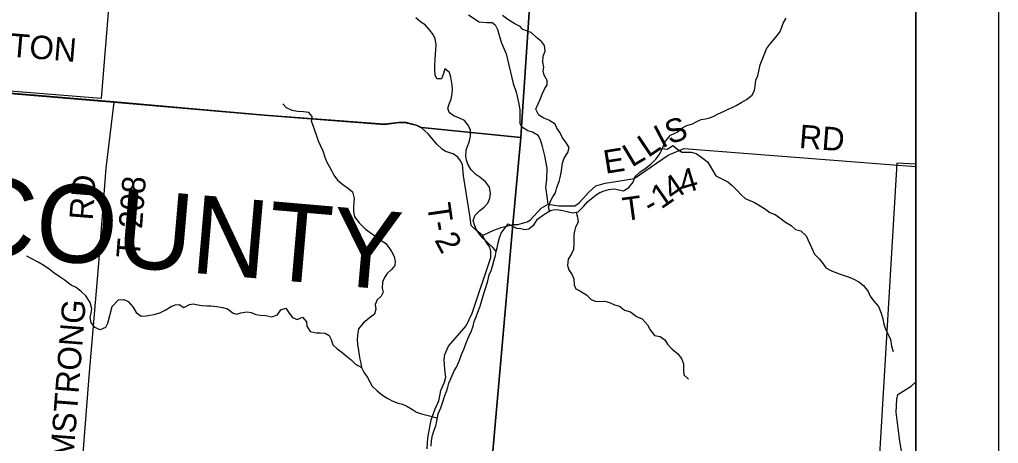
# Model space of a CAD drawing. Extents: x 0 to 42.5, y 0 to 22.
# Drawn here: x 7.815 to 9, y 18.213 to 18.727 of the extents above; entities that cross this region are included whole.
import ezdxf

# ---------------------------------------------------------------- set-up
doc = ezdxf.new("R2010")
doc.units = 0
for name, color, linetype in [('GM_X_County_Text', 7, 'Continuous'), ('GM_X_Interchange_Ramps', 7, 'Continuous'), ('GM_X_Minor_River', 7, 'Continuous'), ('GM_X_Section', 7, 'Continuous'), ('GM_X_Township', 7, 'Continuous'), ('GM_X_Township_Road', 7, 'Continuous'), ('GM_X_Township_Road_Text', 7, 'Continuous'), ('GM_X_Unincorporated', 7, 'Continuous'), ('SH_Cut_Line', 7, 'Continuous'), ('SH_Data', 7, 'Continuous')]:
    doc.layers.add(name, color=color, linetype=linetype)

msp = doc.modelspace()

# ---------------------------------------------------------------- linework, layer by layer
at = {"layer": 'GM_X_Interchange_Ramps'}
for points in [[(7.6874, 18.6472), (7.929, 18.6269), (8.111, 18.6109), (8.2565, 18.5997), (8.2741, 18.602), (8.283, 18.6019), (8.295, 18.5988), (8.3015, 18.5957), (8.4216, 18.5836), (8.4225, 18.5968), (8.4553, 19.0856), (8.4644, 19.2057), (8.5155, 19.8538)], [(8.9, 15.5376), (8.9, 19.0538), (8.8021, 19.0608), (8.7971, 19.0612), (8.4553, 19.0856), (8.4225, 18.5968), (8.4216, 18.5836), (8.4123, 18.4784), (8.3832, 18.1485), (8.3379, 17.6339), (8.308, 17.2922), (8.3087, 17.2846), (8.3084, 17.2765), (8.3074, 17.2694), (8.2902, 17.0877), (8.2877, 17.0646), (8.2823, 16.9912), (8.274, 16.8923), (8.2572, 16.7056), (8.248, 16.5943), (8.2478, 16.5901), (8.1793, 15.7911)]]:
    msp.add_lwpolyline(points, dxfattribs=at)
at = {"layer": 'GM_X_Minor_River'}
for p, q in [((8.4342, 18.711), (8.4242, 18.7146)), ((8.4406, 18.7047), (8.4342, 18.711)), ((8.447, 18.6999), (8.4406, 18.7047)), ((8.4506, 18.695), (8.447, 18.6999)), ((8.4511, 18.6882), (8.4506, 18.695)), ((8.4486, 18.6751), (8.4487, 18.6821)), ((8.4487, 18.6821), (8.4511, 18.6882)), ((8.4496, 18.669), (8.4486, 18.6751)), ((8.449, 18.6643), (8.4496, 18.669)), ((8.4501, 18.6591), (8.449, 18.6643)), ((8.4537, 18.6529), (8.4501, 18.6591)), ((8.4475, 18.6364), (8.4506, 18.6423)), ((8.4506, 18.6423), (8.4536, 18.6477)), ((8.4536, 18.6477), (8.4537, 18.6529)), ((8.4427, 18.6246), (8.4456, 18.6311)), ((8.4456, 18.6311), (8.4475, 18.6364)), ((8.4401, 18.618), (8.4427, 18.6246)), ((8.4436, 18.6108), (8.4401, 18.618)), ((8.4497, 18.607), (8.4436, 18.6108)), ((8.4556, 18.6045), (8.4497, 18.607)), ((8.4633, 18.5999), (8.4556, 18.6045)), ((8.4652, 18.595), (8.4633, 18.5999)), ((8.4695, 18.5893), (8.4652, 18.595)), ((8.4723, 18.5832), (8.4695, 18.5893)), ((8.4763, 18.5779), (8.4723, 18.5832)), ((8.4805, 18.5714), (8.4763, 18.5779)), ((8.4787, 18.5653), (8.4805, 18.5714)), ((8.5931, 18.5704), (8.5995, 18.5696)), ((8.5995, 18.5696), (8.6058, 18.5738)), ((8.6058, 18.5738), (8.6115, 18.5696)), ((8.4722, 18.5527), (8.4741, 18.5587)), ((8.4741, 18.5587), (8.4787, 18.5653)), ((8.6115, 18.5696), (8.6166, 18.5659)), ((8.6166, 18.5659), (8.623, 18.5661)), ((8.623, 18.5661), (8.6281, 18.5659)), ((8.6281, 18.5659), (8.634, 18.5644)), ((8.634, 18.5644), (8.6408, 18.5594)), ((8.6408, 18.5594), (8.6476, 18.5541)), ((8.4707, 18.5409), (8.4714, 18.5464)), ((8.4714, 18.5464), (8.4722, 18.5527)), ((8.6476, 18.5541), (8.6512, 18.5491)), ((8.6512, 18.5491), (8.654, 18.5442)), ((8.4682, 18.5305), (8.4695, 18.5352)), ((8.4695, 18.5352), (8.4707, 18.5409)), ((8.654, 18.5442), (8.658, 18.5373)), ((8.658, 18.5373), (8.6661, 18.5331)), ((8.4637, 18.5168), (8.4655, 18.5231)), ((8.4655, 18.5231), (8.4682, 18.5305)), ((8.6661, 18.5331), (8.6725, 18.5301)), ((8.6725, 18.5301), (8.6778, 18.5253)), ((8.6778, 18.5253), (8.6841, 18.5192)), ((8.4578, 18.5066), (8.4605, 18.5117)), ((8.4605, 18.5117), (8.4637, 18.5168)), ((8.6841, 18.5192), (8.6882, 18.5145)), ((8.6882, 18.5145), (8.6933, 18.5099)), ((8.4553, 18.4991), (8.4578, 18.5066)), ((8.4565, 18.4946), (8.4553, 18.4991)), ((8.6933, 18.5099), (8.699, 18.5074)), ((8.699, 18.5074), (8.7045, 18.5049)), ((8.7045, 18.5049), (8.7094, 18.5019)), ((8.7094, 18.5019), (8.7168, 18.4977)), ((8.4889, 18.4931), (8.4904, 18.4873)), ((8.4904, 18.4873), (8.4913, 18.4809)), ((8.7168, 18.4977), (8.7232, 18.4927)), ((8.7232, 18.4927), (8.7297, 18.4902)), ((8.7297, 18.4902), (8.7355, 18.4862)), ((8.4913, 18.4809), (8.488, 18.475)), ((8.7355, 18.4862), (8.7423, 18.4809)), ((8.7423, 18.4809), (8.7489, 18.4771)), ((8.7489, 18.4771), (8.7544, 18.4723)), ((8.4869, 18.4703), (8.4861, 18.4656)), ((8.4861, 18.4656), (8.4861, 18.4595)), ((8.488, 18.475), (8.4869, 18.4703)), ((8.7544, 18.4723), (8.7607, 18.4706)), ((8.7607, 18.4706), (8.7673, 18.4643)), ((8.7673, 18.4643), (8.7737, 18.4502)), ((8.4859, 18.4546), (8.4856, 18.4481)), ((8.4861, 18.4595), (8.4859, 18.4546)), ((8.4828, 18.4417), (8.4792, 18.4362)), ((8.4856, 18.4481), (8.4828, 18.4417)), ((8.7737, 18.4502), (8.7772, 18.4422)), ((8.7772, 18.4422), (8.7829, 18.4367)), ((8.4792, 18.4362), (8.4784, 18.4284)), ((8.4784, 18.4284), (8.4799, 18.4233)), ((8.7829, 18.4367), (8.788, 18.4306)), ((8.788, 18.4306), (8.7912, 18.4257)), ((8.4799, 18.4233), (8.484, 18.4174)), ((8.484, 18.4174), (8.4859, 18.4123)), ((8.7912, 18.4257), (8.7978, 18.4221)), ((8.7978, 18.4221), (8.8031, 18.4202)), ((8.8031, 18.4202), (8.8086, 18.418)), ((8.8086, 18.418), (8.8143, 18.4159)), ((8.4859, 18.4123), (8.4864, 18.4052)), ((8.4864, 18.4052), (8.4885, 18.4003)), ((8.8143, 18.4159), (8.8192, 18.4142)), ((8.8192, 18.4142), (8.8249, 18.4121)), ((8.8249, 18.4121), (8.8308, 18.4089)), ((8.8308, 18.4089), (8.8368, 18.4043)), ((8.8368, 18.4043), (8.8423, 18.3971)), ((8.4885, 18.4003), (8.4934, 18.3978)), ((8.4934, 18.3978), (8.5014, 18.3929)), ((8.5014, 18.3929), (8.5068, 18.3872)), ((8.8423, 18.3971), (8.8449, 18.3914)), ((8.5068, 18.3872), (8.5119, 18.3852)), ((8.5119, 18.3852), (8.5178, 18.385)), ((8.5178, 18.385), (8.5233, 18.3854)), ((8.5233, 18.3854), (8.529, 18.3835)), ((8.529, 18.3835), (8.5351, 18.3808)), ((8.5351, 18.3808), (8.5411, 18.3792)), ((8.8449, 18.3914), (8.8491, 18.3855)), ((8.8491, 18.3855), (8.8547, 18.3788)), ((8.5411, 18.3792), (8.5474, 18.3745)), ((8.5474, 18.3745), (8.5547, 18.3722)), ((8.5547, 18.3722), (8.5617, 18.3668)), ((8.8547, 18.3788), (8.8581, 18.3706)), ((8.8581, 18.3706), (8.86, 18.364)), ((8.5617, 18.3668), (8.5686, 18.364)), ((8.5686, 18.364), (8.5753, 18.3567)), ((8.86, 18.364), (8.8611, 18.3573)), ((8.8611, 18.3573), (8.863, 18.3526)), ((8.5753, 18.3567), (8.5782, 18.3505)), ((8.5782, 18.3505), (8.5838, 18.3438)), ((8.863, 18.3526), (8.866, 18.3459)), ((8.866, 18.3459), (8.8695, 18.3387)), ((8.5838, 18.3438), (8.5906, 18.3426)), ((8.5906, 18.3426), (8.5961, 18.3386)), ((8.5961, 18.3386), (8.5995, 18.3333)), ((8.5995, 18.3333), (8.6048, 18.3276)), ((8.8695, 18.3387), (8.8707, 18.3309)), ((8.6048, 18.3276), (8.6118, 18.3213)), ((8.6118, 18.3213), (8.6163, 18.3158)), ((8.8707, 18.3309), (8.8727, 18.3243)), ((8.6163, 18.3158), (8.6188, 18.3092)), ((8.6188, 18.3092), (8.6187, 18.3019)), ((8.6187, 18.3019), (8.6193, 18.2961)), ((8.6193, 18.2961), (8.6248, 18.2909))]:
    msp.add_line(p, q, dxfattribs=at)
for points in [[(8.3607, 18.5853), (8.361, 18.5929), (8.3577, 18.5992), (8.3535, 18.6041), (8.3466, 18.6076), (8.3411, 18.6095), (8.3349, 18.614), (8.3336, 18.6193), (8.3353, 18.6253), (8.3375, 18.6303), (8.3387, 18.6369), (8.3389, 18.6418), (8.3388, 18.6471), (8.3379, 18.6519), (8.3371, 18.6568), (8.3353, 18.6623), (8.3298, 18.6669), (8.3283, 18.6611), (8.3259, 18.6546), (8.32, 18.6547), (8.318, 18.6594), (8.3177, 18.6661), (8.3175, 18.6716), (8.3182, 18.6782), (8.3186, 18.685), (8.319, 18.69), (8.3191, 18.6966), (8.318, 18.7031), (8.3156, 18.7084), (8.3113, 18.7141), (8.3058, 18.7203), (8.3009, 18.7233), (8.2947, 18.7289)], [(8.4242, 18.7146), (8.4233, 18.7156), (8.421, 18.7181), (8.4144, 18.7214), (8.4061, 18.7266), (8.3995, 18.7316)], [(8.4066, 18.4791), (8.4164, 18.4738), (8.4219, 18.4732), (8.4266, 18.4722), (8.4313, 18.4728), (8.438, 18.4781), (8.442, 18.4847), (8.4481, 18.489), (8.4528, 18.4924), (8.4576, 18.4952), (8.4625, 18.4966), (8.4678, 18.4962), (8.4726, 18.4954), (8.4796, 18.4935), (8.4849, 18.4923), (8.4911, 18.4936), (8.4978, 18.5), (8.5029, 18.5063), (8.5128, 18.5142), (8.5176, 18.517), (8.5227, 18.5189), (8.5284, 18.5206), (8.5347, 18.5215), (8.546, 18.5192), (8.5525, 18.523), (8.5576, 18.5296), (8.5599, 18.536), (8.5657, 18.5417), (8.5723, 18.5462), (8.579, 18.5513), (8.5852, 18.5573), (8.5891, 18.5628), (8.5919, 18.5679), (8.5942, 18.5729), (8.5969, 18.5791), (8.603, 18.5865), (8.611, 18.5902), (8.6178, 18.5959), (8.6228, 18.5984), (8.6296, 18.6002), (8.6347, 18.6031), (8.64, 18.6053), (8.6454, 18.6064), (8.6507, 18.6077), (8.6554, 18.6096), (8.6607, 18.6122), (8.667, 18.6151), (8.6729, 18.6181), (8.6776, 18.6201), (8.6824, 18.6224), (8.6894, 18.6267), (8.6951, 18.6296), (8.7018, 18.6348), (8.7048, 18.6411), (8.7056, 18.646), (8.7062, 18.6532), (8.7087, 18.6583), (8.7099, 18.6642), (8.7116, 18.6718), (8.7149, 18.6799), (8.7173, 18.6858), (8.7193, 18.6911), (8.724, 18.6975), (8.7305, 18.7053), (8.7353, 18.7115), (8.7379, 18.7174), (8.7395, 18.7221), (8.7429, 18.7284)], [(8.1683, 18.603), (8.1692, 18.6092), (8.1652, 18.614), (8.1588, 18.6148), (8.1514, 18.615), (8.1448, 18.6166), (8.138, 18.6197), (8.1335, 18.6245)], [(8.1684, 18.603), (8.1749, 18.5845), (8.1766, 18.5796), (8.1788, 18.5745), (8.182, 18.5674), (8.1849, 18.5587), (8.1869, 18.5538), (8.19, 18.5483), (8.1926, 18.5435), (8.1955, 18.5382), (8.1998, 18.5321), (8.2062, 18.5268), (8.2131, 18.522), (8.2178, 18.518), (8.2201, 18.5099), (8.2197, 18.5051), (8.2193, 18.4989), (8.2193, 18.4939), (8.2204, 18.4877), (8.2259, 18.4803), (8.2337, 18.4727), (8.2393, 18.4685), (8.2477, 18.4624), (8.2526, 18.4588), (8.2581, 18.4557), (8.2619, 18.4504), (8.2653, 18.4457), (8.2683, 18.4396), (8.2698, 18.4333), (8.2694, 18.4286), (8.2651, 18.4236), (8.2596, 18.4183), (8.2563, 18.4132), (8.2544, 18.4085), (8.254, 18.4011), (8.2553, 18.3963), (8.2529, 18.3912), (8.2479, 18.3869), (8.2456, 18.3812), (8.2462, 18.3757), (8.2445, 18.3694), (8.238, 18.3647), (8.231, 18.3588), (8.2253, 18.3518), (8.2241, 18.3442), (8.2237, 18.3383), (8.2241, 18.333), (8.2252, 18.3254), (8.226, 18.3199), (8.2269, 18.315), (8.2281, 18.31), (8.2288, 18.3051), (8.2316, 18.2992), (8.236, 18.2926), (8.2388, 18.2876), (8.242, 18.2821), (8.2479, 18.2766), (8.2545, 18.2715), (8.2606, 18.2673), (8.2669, 18.2639), (8.2733, 18.2618), (8.2784, 18.2604), (8.2837, 18.2581), (8.2906, 18.2541), (8.2955, 18.2507), (8.3017, 18.2486), (8.308, 18.2471), (8.3206, 18.2437)], [(8.392, 18.4454), (8.3879, 18.4502), (8.3822, 18.4557), (8.3757, 18.4618), (8.3718, 18.4667), (8.3682, 18.4716), (8.3659, 18.4766), (8.3642, 18.483), (8.3667, 18.4897), (8.372, 18.4952), (8.3773, 18.4991), (8.3817, 18.5039), (8.3844, 18.5101), (8.3851, 18.516), (8.384, 18.5234), (8.3789, 18.5301), (8.3721, 18.5356), (8.3673, 18.5388), (8.3617, 18.5445), (8.3575, 18.5514), (8.356, 18.5561), (8.3554, 18.5612), (8.3556, 18.5682), (8.3572, 18.573), (8.3592, 18.5779), (8.3607, 18.5853)], [(8.3132, 18.2097), (8.3138, 18.2161), (8.315, 18.2228), (8.3167, 18.2288), (8.3188, 18.234), (8.3199, 18.2397), (8.3217, 18.2486), (8.3249, 18.2562), (8.3274, 18.2634), (8.3299, 18.2708), (8.3316, 18.2757), (8.3335, 18.2812), (8.3348, 18.2861), (8.3375, 18.2924), (8.3409, 18.3007), (8.3438, 18.3055), (8.3472, 18.3127), (8.3499, 18.3206), (8.3531, 18.3278), (8.3558, 18.3348), (8.359, 18.3426), (8.3619, 18.3494), (8.364, 18.3551), (8.3653, 18.3606), (8.3678, 18.3665), (8.3699, 18.3718), (8.3724, 18.3794), (8.3741, 18.3849), (8.3762, 18.3917), (8.3779, 18.397), (8.38, 18.4031), (8.3817, 18.4101), (8.3836, 18.4173), (8.3859, 18.4225), (8.3874, 18.4278), (8.3895, 18.4355), (8.3911, 18.4405), (8.392, 18.4454), (8.393, 18.4501), (8.3945, 18.4562), (8.396, 18.4621), (8.3981, 18.4678), (8.4063, 18.479)], [(7.9265, 18.3784), (7.9214, 18.3583), (7.9189, 18.3532), (7.9124, 18.3505), (7.9062, 18.3533), (7.9017, 18.3596), (7.9005, 18.3654), (7.9017, 18.3713), (7.9023, 18.3761), (7.9002, 18.3837), (7.895, 18.3919), (7.8897, 18.3967), (7.8836, 18.402), (7.8775, 18.4047), (7.8691, 18.4111), (7.8641, 18.4145), (7.8565, 18.4195), (7.8509, 18.4239), (7.8444, 18.4284), (7.8376, 18.4324), (7.8299, 18.4368), (7.8236, 18.4397)], [(7.9265, 18.3784), (7.9345, 18.3869), (7.941, 18.3873), (7.9463, 18.3848), (7.9521, 18.3785), (7.9561, 18.3717), (7.962, 18.3671), (7.9681, 18.3675), (7.9728, 18.3684), (7.9779, 18.369), (7.9846, 18.3712), (7.9912, 18.3743), (7.9984, 18.379), (8.0032, 18.3809), (8.0081, 18.3813), (8.0136, 18.3776), (8.0208, 18.3814), (8.0256, 18.3822), (8.0307, 18.3808), (8.0356, 18.3799), (8.0417, 18.3795), (8.0464, 18.3795), (8.0538, 18.3789), (8.0605, 18.3776), (8.0665, 18.376), (8.0734, 18.3709), (8.0781, 18.3697), (8.083, 18.3711), (8.0902, 18.3722), (8.0952, 18.3716), (8.1009, 18.3693), (8.1064, 18.3684), (8.113, 18.3678), (8.1202, 18.3662), (8.127, 18.3689), (8.1314, 18.3746), (8.1373, 18.3768), (8.1413, 18.3706), (8.1453, 18.3656), (8.1509, 18.3631), (8.1574, 18.3658), (8.1621, 18.3601), (8.1629, 18.3551), (8.1668, 18.3487), (8.1744, 18.3468), (8.1794, 18.3468), (8.1849, 18.3464), (8.1898, 18.3437), (8.1923, 18.339), (8.1941, 18.3323), (8.1993, 18.3276), (8.2049, 18.3234), (8.2104, 18.319), (8.2165, 18.3142), (8.2218, 18.3089), (8.2288, 18.3051)]]:
    msp.add_lwpolyline(points, dxfattribs=at)
at = {"layer": 'GM_X_Section'}
msp.add_lwpolyline([(7.4474, 19.1773), (7.955, 19.138), (7.9137, 18.631), (7.4421, 18.6691), (7.4064, 18.6718)], close=True, dxfattribs=at)
at = {"layer": 'GM_X_Township'}
msp.add_lwpolyline([(7.6874, 18.6472), (7.929, 18.6269), (8.111, 18.6109), (8.2565, 18.5997), (8.2741, 18.602), (8.283, 18.6019), (8.295, 18.5988), (8.3015, 18.5957), (8.4216, 18.5836), (8.4123, 18.4784), (8.3832, 18.1485), (8.3379, 17.6339), (8.308, 17.2922)], dxfattribs=at)
at = {"layer": 'GM_X_Township_Road'}
msp.add_line((7.9292, 18.6266), (7.9617, 18.6238), dxfattribs=at)
for points in [[(8.3585, 18.7322), (8.3714, 18.7239), (8.3806, 18.723), (8.387, 18.723), (8.3907, 18.7202), (8.3935, 18.7147), (8.3981, 18.6991), (8.4039, 18.685), (8.4125, 18.6492), (8.416, 18.6385), (8.4194, 18.6245), (8.4207, 18.6169), (8.4204, 18.6009), (8.4226, 18.5966)], [(7.3505, 18.6762), (7.4024, 18.6716), (7.4512, 18.6662), (7.5068, 18.6617), (7.5691, 18.6559), (7.6875, 18.6469), (7.9292, 18.6266)], [(7.9292, 18.6266), (7.9194, 18.5467), (7.9101, 18.4262), (7.8988, 18.2941), (7.8789, 18.0407)], [(7.9617, 18.6238), (8.1112, 18.6107), (8.2566, 18.5994), (8.2742, 18.6017), (8.2831, 18.6016), (8.2951, 18.5985), (8.3016, 18.5954)], [(8.3753, 18.4648), (8.3648, 18.4736), (8.3615, 18.4769), (8.3599, 18.4893), (8.3524, 18.5373), (8.3511, 18.551), (8.3488, 18.5552), (8.3454, 18.5597), (8.3399, 18.5637), (8.3307, 18.5668), (8.3264, 18.5695), (8.32, 18.5756), (8.3098, 18.588), (8.3016, 18.5954)], [(8.455, 18.5028), (8.4538, 18.512), (8.4522, 18.5234), (8.4533, 18.5327), (8.4535, 18.5464), (8.451, 18.5614), (8.4479, 18.5726), (8.4455, 18.5807), (8.4429, 18.586), (8.4359, 18.5901), (8.4304, 18.5917), (8.4226, 18.5966)], [(8.4124, 18.4782), (8.4181, 18.4782), (8.4295, 18.4813), (8.4333, 18.4837), (8.4466, 18.4982), (8.455, 18.5028), (8.4678, 18.501), (8.4777, 18.5009), (8.487, 18.5007), (8.4925, 18.5043), (8.5045, 18.518), (8.5124, 18.5251), (8.5238, 18.5284), (8.5467, 18.5318), (8.559, 18.5339), (8.6003, 18.5621), (8.6192, 18.5704), (8.868, 18.5509), (8.9, 18.5484)], [(8.3753, 18.4648), (8.389, 18.4712), (8.3978, 18.4744), (8.4124, 18.4782)], [(8.3082, 18.2062), (8.3093, 18.2195), (8.3134, 18.2415), (8.3181, 18.2546), (8.3224, 18.2646), (8.3241, 18.2727), (8.325, 18.277), (8.3293, 18.2872), (8.3311, 18.293), (8.3299, 18.3024), (8.3289, 18.3145), (8.3296, 18.3208), (8.3344, 18.3308), (8.3558, 18.3553), (8.3628, 18.3708), (8.3856, 18.4384), (8.3853, 18.446), (8.3844, 18.4506), (8.38, 18.4569), (8.3753, 18.4648)], [(8.8846, 18.191), (8.8801, 18.2183), (8.8762, 18.2508), (8.8769, 18.2665), (8.8784, 18.2723), (8.8943, 18.2822), (8.9, 18.2874)]]:
    msp.add_lwpolyline(points, dxfattribs=at)
at = {"layer": 'GM_X_Unincorporated'}
msp.add_lwpolyline([(8.9, 18.101), (8.9, 18.5512), (8.8772, 18.5527), (8.8503, 18.1041)], close=True, dxfattribs=at)
at = {"layer": 'SH_Cut_Line'}
for points in [[(7.6874, 18.6472), (7.929, 18.6269), (8.111, 18.6109), (8.2565, 18.5997), (8.2741, 18.602), (8.283, 18.6019), (8.295, 18.5988), (8.3015, 18.5957), (8.4216, 18.5836), (8.4225, 18.5968), (8.4553, 19.0856), (8.7971, 19.0612), (8.8021, 19.0608), (8.9, 19.0538), (8.9, 20.9)], [(8.9, 14.1), (8.9, 19.0538), (8.8021, 19.0608), (8.7971, 19.0612), (8.4553, 19.0856), (8.4225, 18.5968), (8.4216, 18.5836), (8.4123, 18.4784), (8.3832, 18.1485), (8.3379, 17.6339), (8.308, 17.2922), (8.3087, 17.2846), (8.3084, 17.2765), (8.3074, 17.2694), (8.2902, 17.0877), (8.2877, 17.0646), (8.2823, 16.9912), (8.274, 16.8923), (8.2572, 16.7056), (8.248, 16.5943), (8.2478, 16.5901), (8.1793, 15.7911)], [(8.308, 17.2922), (8.3379, 17.6339), (8.3832, 18.1485), (8.4123, 18.4784), (8.4216, 18.5836), (8.3015, 18.5957), (8.295, 18.5988), (8.283, 18.6019), (8.2741, 18.602), (8.2565, 18.5997), (8.111, 18.6109), (7.929, 18.6269), (7.6874, 18.6472)]]:
    msp.add_lwpolyline(points, dxfattribs=at)
at = {"layer": 'SH_Data'}
for p, q in [((9, 21), (9, 14)), ((8.9, 20.9), (8.9, 14.1))]:
    msp.add_line(p, q, dxfattribs=at)

# ---------------------------------------------------------------- texts
at = {"layer": 'GM_X_County_Text'}
msp.add_text('PICKAWAY COUNTY', height=0.094697, rotation=355.0676, dxfattribs=at).set_placement((7.0392, 18.5047))
at = {"layer": 'GM_X_Township_Road_Text'}
for s, height, rotation, p in [('TARLTON', 0.02841, 355.285, (7.706, 18.6898)), ('S', 0.0284, 18.8241, (8.602, 18.5751)), ('I', 0.0284, 27.6647, (8.5927, 18.5701)), ('RD', 0.02841, 355.5641, (8.758, 18.5711)), ('L', 0.0284, 33.7995, (8.5757, 18.5587)), ('E', 0.0284, 9.1065, (8.5242, 18.5396)), ('L', 0.0284, 30.9297, (8.5562, 18.547)), ('4', 0.0284, 16.631, (8.6183, 18.5151)), ('RD', 0.02841, 85.5622, (7.9034, 18.4828)), ('T-208', 0.02841, 85.5146, (7.9603, 18.4368)), ('4', 0.0284, 34.4911, (8.606, 18.5061)), ('1', 0.0284, 34.7272, (8.5917, 18.4962)), ('T', 0.0284, 7.6422, (8.5469, 18.4824)), ('T', 0.0284, 278.1616, (8.3082, 18.5025)), ('-', 0.0284, 29.4683, (8.5791, 18.4889)), ('-', 0.0284, 279.7582, (8.3114, 18.4806)), ('2', 0.0284, 298.6062, (8.3167, 18.4595)), ('ARMSTRONG', 0.02841, 85.5088, (7.8759, 18.1402))]:
    msp.add_text(s, height=height, rotation=rotation, dxfattribs=at).set_placement(p)

doc.saveas('drawing.dxf')
